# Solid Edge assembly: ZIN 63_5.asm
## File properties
Title: Zylinder
Author: bmolnar
Template: iso metric assembly.asm
Last saved by: bmolnar
Revision: 6
Application: Solid Edge
Username: bmolnar
Dokumentum tartalom típus: 1
Document Number: ZIN 63/5
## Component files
Kit_1.par
Kit_2.par
Kolbenstange.par
Profilrohr.par
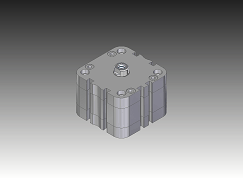
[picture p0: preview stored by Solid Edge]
